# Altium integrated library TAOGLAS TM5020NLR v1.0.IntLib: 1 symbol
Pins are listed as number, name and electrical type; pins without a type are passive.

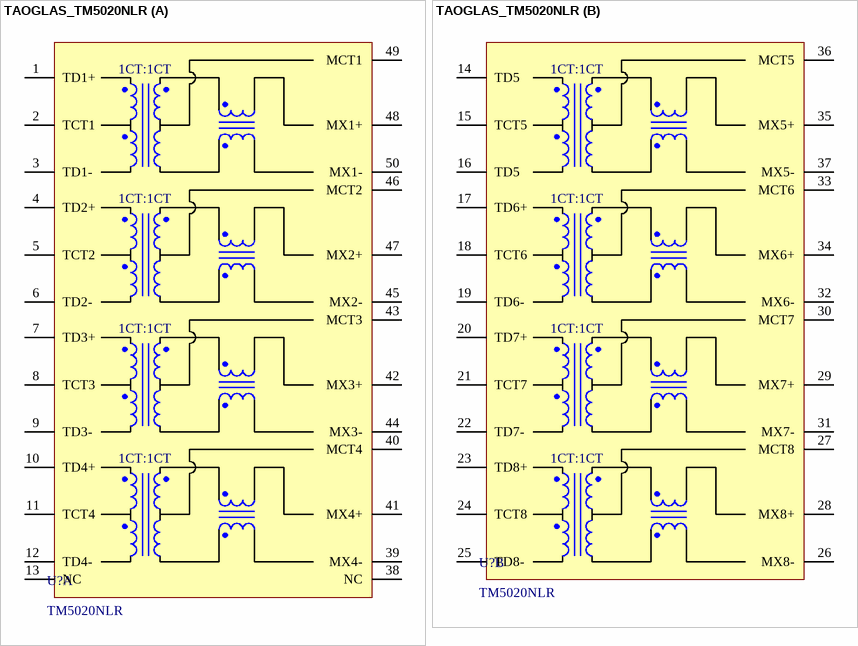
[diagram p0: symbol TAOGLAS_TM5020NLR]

## TAOGLAS_TM5020NLR
designator U?, comment TM5020NLR
Dual 1000 Base-T/1G transformer Dual Port and 50pin SMT with PoE; ComponentLibStatus: Created; MFG: Taoglas; Temp_High: +85C; Temp_Low: -40C
footprint TAOGLAS_TM5020NLR (Dual 1000 Base-T/1G transformer Dual Port and 50pin SMT with PoE)
part A pins: 1 TD1+, 2 TCT1, 3 TD1-, 4 TD2+, 5 TCT2, 6 TD2-, 7 TD3+, 8 TCT3, 9 TD3-, 10 TD4+, 11 TCT4, 12 TD4-, 13 NC, 38 NC, 39 MX4-, 40 MCT4, 41 MX4+, 42 MX3+, 43 MCT3, 44 MX3-, 45 MX2-, 46 MCT2, 47 MX2+, 48 MX1+, 49 MCT1, 50 MX1-
part B pins: 14 TD5, 15 TCT5, 16 TD5, 17 TD6+, 18 TCT6, 19 TD6-, 20 TD7+, 21 TCT7, 22 TD7-, 23 TD8+, 24 TCT8, 25 TD8-, 26 MX8-, 27 MCT8, 28 MX8+, 29 MX7+, 30 MCT7, 31 MX7-, 32 MX6-, 33 MCT6, 34 MX6+, 35 MX5+, 36 MCT5, 37 MX5-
